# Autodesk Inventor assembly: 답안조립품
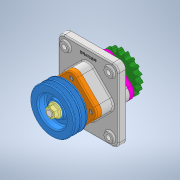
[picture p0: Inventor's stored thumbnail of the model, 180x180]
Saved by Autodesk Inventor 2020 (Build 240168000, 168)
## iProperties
Created: 2021-07
Part Number: 답안조립품
Document SubType Name: Assembly
Designer: Owner
Author: Owner
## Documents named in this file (16)
- C:\Users\Owner\Desktop\710707V1008\답안조립품.iam
- C:\Users\Owner\Desktop\710707V1008\본체.ipt
- C:\Users\Owner\Desktop\710707V1008\M16 너트.ipt
- C:\Users\Owner\Desktop\710707V1008\Ű 6x6x18.ipt
- C:\Users\Owner\Desktop\710707V1008\Ű 6x6x20.ipt
- C:\Users\Owner\Desktop\710707V1008\V-벨트풀리.ipt
- C:\Users\Owner\Desktop\710707V1008\멈춤나사 M4.ipt
- C:\Users\Owner\Desktop\710707V1008\베어링 6206.ipt
- C:\Users\Owner\Desktop\710707V1008\볼트 M6.ipt
- C:\Users\Owner\Desktop\710707V1008\부시.ipt
- C:\Users\Owner\Desktop\710707V1008\오일실 30x42x8.ipt
- C:\Users\Owner\Desktop\710707V1008\오일실 30x45x8.ipt
- C:\Users\Owner\Desktop\710707V1008\체인 스프로킷.ipt
- C:\Users\Owner\Desktop\710707V1008\축.ipt
- C:\Users\Owner\Desktop\710707V1008\커버A.ipt
- C:\Users\Owner\Desktop\710707V1008\커버B.ipt
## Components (4 placed, 3 different names)
1. M16 너트:1
2. Ű 6x6x20:1 — 각도:2
3. V-벨트풀리:1 — 각도:1
4. M16 너트:2
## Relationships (2: Angle 2)
- 각도:1 [Angle]: V-벨트풀리:1
- 각도:2 [Angle]: Ű 6x6x20:1
